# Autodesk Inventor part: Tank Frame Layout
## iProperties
Created: 2007-04
Part Number: Tank Frame Layout
Document SubType Name: Modeling
Designer: Admin
Density: 1 g/cm^3
Surface Area: 59500 cm^2
SpraySideWidth: 600.000 mm
Diameter: 620.000 mm
Author: Admin
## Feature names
1. Extrusion1
